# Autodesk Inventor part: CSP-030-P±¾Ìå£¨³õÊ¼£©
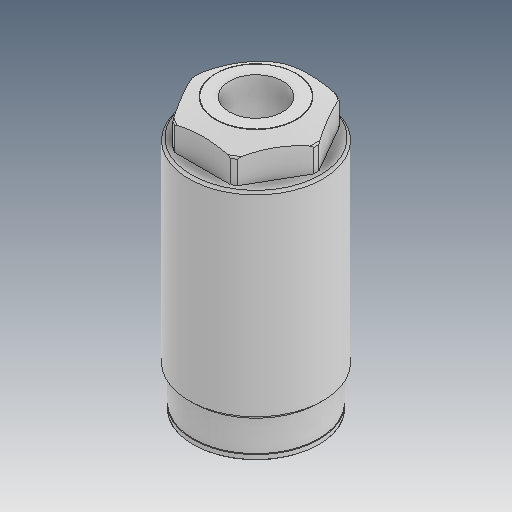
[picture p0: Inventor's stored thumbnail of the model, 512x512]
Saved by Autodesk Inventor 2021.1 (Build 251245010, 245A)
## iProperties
Created: 2019-01
Part Number: CSP-030-P±¾Ìå£¨³õÊ¼£©
Material: Ogólny
Document SubType Name: Modeling
Designer: user
Density: 1 g/cm^3
Appearance: Domyślna
Author: user
Revision Number: ÈÎºÎ
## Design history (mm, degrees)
feature "ÇÐ³ý-À­Éì5"
node "Bryła1"
